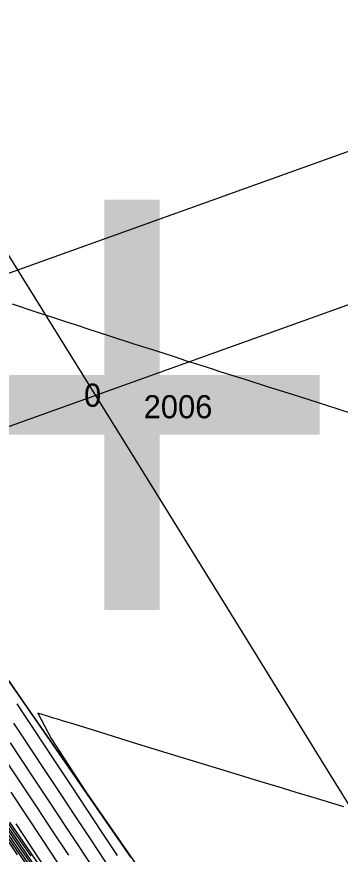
# Model space of a CAD drawing. Extents: x 74655 to 77873, y 48844 to 50507.
# Drawn here: x 75176.222 to 75177.904, y 49695.589 to 49699.942 of the extents above; entities that cross this region are included whole.
import ezdxf

# ---------------------------------------------------------------- set-up
doc = ezdxf.new("R2010")
doc.units = 0
for name, color, linetype in [('2', 7, 'Continuous'), ('24', 7, 'Continuous'), ('50', 7, 'Continuous'), ('62', 7, 'Continuous'), ('7', 7, 'Continuous')]:
    doc.layers.add(name, color=color, linetype=linetype)

msp = doc.modelspace()

# ---------------------------------------------------------------- linework, layer by layer
at = {"layer": '2'}
for radius in [829.5111, 818.5111, 807.5111, 803.5111]:
    msp.add_arc((74494.001, 49274.1292), radius, 30.8050451, 46.6978585, dxfattribs=at)
at = {"layer": '50'}
for points in [[(75176.8156, 49695.5737), (75176.4421, 49696.1124), (75176.0626, 49696.6597), (75175.6772, 49697.2156), (75175.2858, 49697.7801), (75174.9151, 49698.3148), (75174.565, 49698.8196), (75174.2356, 49699.2948), (75173.9062, 49699.7699), (75173.5768, 49700.245)], [(75177.9617, 49697.8803), (75177.834, 49697.9207), (75177.6599, 49697.9759), (75177.52, 49698.0203), (75177.4142, 49698.0539), (75177.3426, 49698.0768), (75177.2845, 49698.0954), (75177.2398, 49698.1097), (75177.2087, 49698.1197), (75177.1643, 49698.134), (75177.1069, 49698.1524), (75177.0362, 49698.1752), (75176.9449, 49698.2047), (75176.833, 49698.2409), (75176.7004, 49698.284), (75176.5986, 49698.317), (75176.5276, 49698.3401), (75176.4876, 49698.3532), (75176.4196, 49698.3754), (75176.3238, 49698.4069), (75176.2, 49698.4475)], [(75176.3308, 49695.5085), (75176.2418, 49695.6376), (75176.1547, 49695.7642), (75176.0693, 49695.8882), (75175.9865, 49696.0085), (75175.9062, 49696.1251), (75175.8284, 49696.238), (75175.7519, 49696.3491), (75175.6766, 49696.4584), (75175.6025, 49696.566), (75175.5258, 49696.6774), (75175.4465, 49696.7926), (75175.3645, 49696.9116), (75175.2809, 49697.033), (75175.1957, 49697.1566), (75175.1089, 49697.2827), (75175.0253, 49697.404), (75174.9449, 49697.5207), (75174.8677, 49697.6328), (75174.8022, 49697.728), (75174.7482, 49697.8063), (75174.6634, 49697.9294)], [(75174.6669, 49697.9429), (75174.8012, 49697.7479), (75174.873, 49697.6438), (75174.9493, 49697.533), (75175.0301, 49697.4156), (75175.1207, 49697.2841), (75175.221, 49697.1385), (75175.331, 49696.9788), (75175.415, 49696.8568), (75175.473, 49696.7726), (75175.5051, 49696.7261), (75175.5596, 49696.6468), (75175.6368, 49696.5348), (75175.7364, 49696.3901), (75175.8243, 49696.2625), (75175.9004, 49696.152), (75175.9647, 49696.0587), (75176.0368, 49695.954), (75176.1167, 49695.838), (75176.2044, 49695.7106), (75176.2954, 49695.5784)], [(75176.3223, 49695.4651), (75176.235, 49695.5919), (75176.1424, 49695.7264), (75176.0445, 49695.8685), (75175.9515, 49696.0035), (75175.8634, 49696.1314), (75175.7803, 49696.2521), (75175.6848, 49696.3907), (75175.577, 49696.5473), (75175.4568, 49696.7218), (75175.3367, 49696.8962), (75175.2165, 49697.0707), (75175.0964, 49697.2451), (75174.9928, 49697.3955), (75174.9057, 49697.5219), (75174.8352, 49697.6243), (75174.7757, 49697.7107), (75174.7274, 49697.7808), (75174.653, 49697.8889)], [(75176.3012, 49695.5143), (75176.2094, 49695.6476), (75176.1226, 49695.7736), (75176.0408, 49695.8924), (75175.9592, 49696.011), (75175.8777, 49696.1293), (75175.7963, 49696.2474), (75175.7015, 49696.3852), (75175.593, 49696.5426), (75175.471, 49696.7197), (75175.35, 49696.8955), (75175.2299, 49697.0698), (75175.1107, 49697.2428), (75175.007, 49697.3934), (75174.9188, 49697.5215), (75174.846, 49697.6272), (75174.7845, 49697.7164), (75174.7343, 49697.7893), (75174.6564, 49697.9024)], [(75174.6599, 49697.9159), (75174.7874, 49697.7309), (75174.8584, 49697.6278), (75174.9367, 49697.5141), (75175.0223, 49697.3898), (75175.1153, 49697.2548), (75175.2157, 49697.109), (75175.3235, 49696.9525), (75175.4052, 49696.8339), (75175.4608, 49696.7532), (75175.4903, 49696.7104), (75175.5504, 49696.623), (75175.6412, 49696.4912), (75175.7626, 49696.315), (75175.8577, 49696.1768), (75175.9266, 49696.0769), (75175.9691, 49696.0151), (75176.0288, 49695.9285), (75176.1056, 49695.817), (75176.1994, 49695.6806), (75176.2942, 49695.5431)], [(75176.2259, 49695.5865), (75176.1324, 49695.7222), (75176.0333, 49695.8662), (75175.9388, 49696.0033), (75175.8492, 49696.1335), (75175.7643, 49696.2568), (75175.6682, 49696.3963), (75175.561, 49696.552), (75175.4426, 49696.7239), (75175.3279, 49696.8904), (75175.2168, 49697.0517), (75175.1093, 49697.2077), (75175.0104, 49697.3514), (75174.9199, 49697.4827), (75174.8379, 49697.6018), (75174.7714, 49697.6983), (75174.7204, 49697.7723), (75174.6495, 49697.8753)], [(75175.8677, 49696.9415), (75176.246, 49696.396), (75176.6107, 49695.8699), (75176.962, 49695.3633)], [(75176.2221, 49696.3709), (75176.2625, 49696.3099), (75176.3039, 49696.2473), (75176.3581, 49696.1654), (75176.4251, 49696.0641), (75176.5049, 49695.9436), (75176.5847, 49695.823), (75176.6644, 49695.7024), (75176.7442, 49695.5819)], [(75177.9222, 49695.836), (75177.7806, 49695.8785), (75177.6745, 49695.9105), (75177.6038, 49695.9318), (75177.5685, 49695.9425), (75177.4862, 49695.9675), (75177.357, 49696.0069), (75177.1808, 49696.0606), (75177.0049, 49696.1144), (75176.8292, 49696.1685), (75176.6537, 49696.2227), (75176.5305, 49696.2607), (75176.4596, 49696.2826), (75176.441, 49696.2884), (75176.4136, 49696.2969), (75176.3776, 49696.3082), (75176.3327, 49696.3222), (75176.4005, 49696.1907), (75176.5809, 49695.9136), (75176.8738, 49695.4911)], [(75176.2054, 49696.2703), (75176.2468, 49696.2077), (75176.301, 49696.1258), (75176.368, 49696.0246), (75176.4478, 49695.904), (75176.5276, 49695.7834), (75176.6073, 49695.6629), (75176.6871, 49695.5423)], [(75176.63, 49695.5027), (75176.5503, 49695.6233), (75176.4705, 49695.7438), (75176.3907, 49695.8644), (75176.3109, 49695.985), (75176.2439, 49696.0862), (75176.1897, 49696.1681)], [(75176.4932, 49695.5837), (75176.4123, 49695.7059), (75176.3303, 49695.8298), (75176.2472, 49695.9554), (75176.1716, 49696.0697)], [(75176.4361, 49695.5441), (75176.3557, 49695.6656), (75176.2747, 49695.788), (75176.193, 49695.9114)], [(75176.3603, 49695.5028), (75176.2743, 49695.6277), (75176.1868, 49695.7548)], [(75176.379, 49695.5045), (75176.2991, 49695.6253), (75176.2191, 49695.7463)]]:
    msp.add_lwpolyline(points, dxfattribs=at)
at = {"layer": '7'}
for p, q in [((74992.787, 49632.7925), (75369.2755, 49767.9087)), ((74993.0404, 49632.0865), (75369.5289, 49767.2028))]:
    msp.add_line(p, q, dxfattribs=at)

# ---------------------------------------------------------------- texts
at = {"layer": '24'}
msp.add_text('+', height=3, dxfattribs=at).set_placement((75175.6516, 49696.4749))
at = {"layer": '62'}
for s, p in [('0', (75176.572, 49697.9149)), ('2006', (75176.882, 49697.8549))]:
    msp.add_text(s, height=0.12, dxfattribs=at).set_placement(p)

doc.saveas('drawing.dxf')
